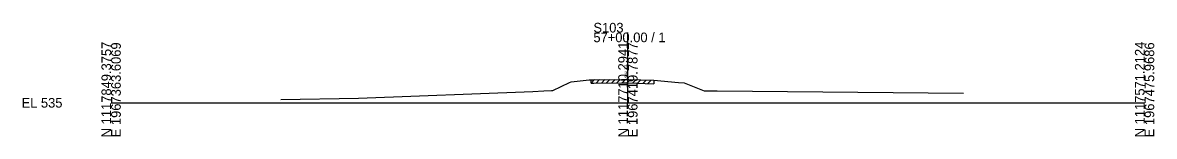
# Model space of a CAD drawing. Extents: x 974 to 1303, y 990 to 14518.
# Drawn here: x 974.3 to 1302.8, y 4490.3 to 4523.2 of the extents above; entities that cross this region are included whole.
import ezdxf

# ---------------------------------------------------------------- set-up
doc = ezdxf.new("R2010")
doc.units = 0
for name, color, linetype in [('Level 10', 7, 'Continuous'), ('Level 60', 7, 'Continuous'), ('Level 61', 7, 'Continuous'), ('Level 63', 7, 'Continuous')]:
    doc.layers.add(name, color=color, linetype=linetype)

msp = doc.modelspace()

# ---------------------------------------------------------------- linework, layer by layer
at = {"layer": 'Level 60'}
for p, q in [((1128.21, 4503.57), (1133.03, 4505.83)), ((1133.03, 4505.83), (1133.57, 4506.07)), ((1133.57, 4506.07), (1138.72, 4506.62)), ((1138.72, 4506.62), (1139.3, 4506.69)), ((1139.3, 4506.69), (1140.15, 4506.69)), ((1140.15, 4506.69), (1148.11, 4506.78)), ((1148.11, 4506.78), (1149.11, 4506.75)), ((1149.11, 4506.75), (1150, 4506.73)), ((1150, 4506.73), (1157.54, 4506.52)), ((1157.54, 4506.52), (1164.69, 4505.92)), ((1164.69, 4505.92), (1166.33, 4505.78)), ((1166.33, 4505.78), (1172.19, 4503.51)), ((1049.22, 4500.92), (1071.81, 4501.37)), ((1071.81, 4501.37), (1122.37, 4503.3)), ((1122.37, 4503.3), (1125.64, 4503.44)), ((1125.64, 4503.44), (1127.86, 4503.56)), ((1127.86, 4503.56), (1128.21, 4503.57)), ((1172.19, 4503.51), (1175.35, 4503.43)), ((1175.35, 4503.43), (1175.94, 4503.45)), ((1175.94, 4503.45), (1247.48, 4502.74))]:
    msp.add_line(p, q, dxfattribs=at)
at = {"layer": 'Level 61'}
for p, q in [((1139.3, 4505.69), (1140.31, 4506.7)), ((1139.3, 4505.69), (1139.3, 4506.69)), ((1139.3, 4505.69), (1140.15, 4505.69)), ((1140.15, 4505.69), (1148.11, 4505.78)), ((1140.8, 4505.7), (1141.81, 4506.71)), ((1142.3, 4505.72), (1143.31, 4506.73)), ((1143.8, 4505.73), (1144.81, 4506.74)), ((1145.3, 4505.75), (1146.31, 4506.76)), ((1146.8, 4505.76), (1147.81, 4506.77)), ((1148.11, 4505.78), (1149.11, 4505.75)), ((1148.3, 4505.77), (1149.28, 4506.75)), ((1149.11, 4505.75), (1150, 4505.73)), ((1149.8, 4505.73), (1150.77, 4506.71)), ((1150, 4505.73), (1157.54, 4505.52)), ((1151.3, 4505.69), (1152.27, 4506.67)), ((1152.8, 4505.65), (1153.77, 4506.62)), ((1154.3, 4505.61), (1155.27, 4506.58)), ((1155.8, 4505.57), (1156.77, 4506.54)), ((1157.54, 4506.52), (1157.54, 4505.52)), ((1157.54, 4505.52), (1157.54, 4505.52))]:
    msp.add_line(p, q, dxfattribs=at)
at = {"layer": 'Level 63'}
for p, q in [((1150, 4500), (1150, 4520.33)), ((1000, 4500), (1150, 4500)), ((1150, 4500), (1300, 4500))]:
    msp.add_line(p, q, dxfattribs=at)

# ---------------------------------------------------------------- texts
at = {"layer": 'Level 10'}
msp.add_text('541.73', height=0.9, rotation=90, dxfattribs=at).set_placement((1149.95, 4507.23))
at = {"layer": 'Level 63'}
for s, p in [('S103', (1140, 4520.33)), ('57+00.00 / 1', (1140, 4517.53)), ('EL 535', (974, 4498.6))]:
    msp.add_text(s, height=2.8, dxfattribs=at).set_placement(p)
for s, p in [('N 1117849.3757', (1000, 4490)), ('N 1117710.2941', (1150, 4490)), ('N 1117571.2124', (1300, 4490)), ('E 1967363.6069', (1002.8, 4490)), ('E 1967419.7877', (1152.8, 4490)), ('E 1967475.9686', (1302.8, 4490))]:
    msp.add_text(s, height=2.8, rotation=90, dxfattribs=at).set_placement(p)

doc.saveas('drawing.dxf')
